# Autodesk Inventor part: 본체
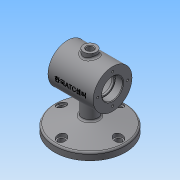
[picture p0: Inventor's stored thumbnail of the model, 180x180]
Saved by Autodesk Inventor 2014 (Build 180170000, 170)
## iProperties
Created: 2018-12
Part Number: 본체
Material: 일반
Document SubType Name: Modeling
Designer: net
Density: 1 g/cm^3
Appearance: 기본값
Mass: 253.122 g
Surface Area: 554.262 cm^2
Volume: 253.122 cm^3
Author: net
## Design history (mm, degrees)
sketch "스케치1"
  geometry: L1 (-35, 0)-(35, 0); L2 (-35, 0)-(-35, 30); L3 (-35, 30)-(35, 30); L4 (35, 30)-(35, 0); L5 (-35, 16)-(-23.3, 16); L6 (-23, 15.7)-(-23, 14); L7 (-23, 14)-(-20, 14); L8 (-20, 14)-(-20, 22); L9 (-17, 25)-(17, 25); L10 (20, 22)-(20, 14); L11 (20, 14)-(23, 14); L12 (23, 14)-(23, 15.7); L13 (23.3, 16)-(35, 16); A1 r 0.3 centre (-23.3, 15.7) between (-23, 15.7) and (-23.3, 16); A2 r 0.3 centre (23.3, 15.7) between (23.3, 16) and (23, 15.7); A3 r 3 centre (17, 22) between (20, 22) and (17, 25); A4 r 3 centre (-17, 22) between (-17, 25) and (-20, 22); 6 further points
  constraints: 26 end point, 10 point on line, 8 point on circle, 8 tangent, 7 parallel, 5 perpendicular, 4 centre point, 2 equal radius, 1 coincident, 1 horizontal, 1 midpoint
  dimensions: "d0" = 70 distance of L1.start L1.end; "d1" = 60 diameter of L3 L1; "d2" = 28 diameter of L7 L1; "d3" = 28 diameter of L11 L1; "d4" = 32 diameter of L5 L1; "d5" = 32 diameter of L13 L1; "d6" = 50 diameter of L9 L1; "d7" = 12 distance of L5.start point (-23, 16); "d8" = 12 distance of point (23, 16) L13.end; "d9" = 40 distance of point (-20, 25) point (20, 25); "d10" = 3 distance of L6.end L7.end; "d11" = 0.3 radius of A1; "d12" = 3 radius of A3
revolve "회전1" sketch "스케치1" stored, may be unused: angle "d13" = 90 deg
sketch "스케치2" dims "d14" = 46
  geometry: C1 r 16 at (0, 0) reference; 2 further points
  constraints: 2 vertical alignment, 1 coincident, 2 other
hole "구멍1" sketch "스케치2" at (0, 23) diameter "d15" = 3.242; stored, may be unused: countersink angle "d19" = 90 deg, drill point angle "d21" = 118 deg; dims "d16" = 8, "d17" = 4, "d18" = 2, "d20" = 10
chamfer "모따기1" distance "d25" = 1; stored, may be unused: second distance "d26" = 2, angle "d27" = 45 deg
node "작업 평면1"
sketch "스케치3"
  geometry: C1 r 55 at (0, 0); 1 further point
  constraints: 1 centre point, 1 coincident
  dimensions: "d29" = 110 diameter of C1
extrude "돌출1" join sketch "스케치3" distance "d30" = 11; taper "d31" = 0 deg
sketch "스케치4"
  geometry: L1 (-75, -55)-(-75, 55) reference; L2 (30, 0)-(-75, 0); L3 (-75, 55)-(-64, 55) reference; L4 (-64, 55)-(-64, -55) reference; L5 (-64, -55)-(-75, -55) reference; L6 (-64, 55)-(-52.478, 12); L7 (-52.478, 12)-(-64, 12); L8 (-64, 55)-(-64, 12); C1 r 25 at (0, 0) reference; 3 further points
  constraints: 8 end point, 2 horizontal alignment, 2 midpoint, 1 collinear, 1 perpendicular, 1 point on line, 1 other
  dimensions: "d39" = 75 deg angle of L6 L3; "d40" = 24 diameter of L6.end L2
revolve "회전2" sketch "스케치4" stored, may be unused: angle "d41" = 90 deg
fillet "모깎기2" dims "d42" = 3
sketch "스케치5"
  geometry: C1 r 12 at (0, 0) reference; C2 r 12 at (0, 0)
  constraints: 1 centre point, 1 coincident, 1 concentric
extrude "돌출2" join sketch "스케치5" stored distance "d43" = 1; taper "d44" = 0 deg
fillet "모깎기3" dims "d45" = 3
node "작업 평면2"
sketch "스케치6"
  geometry: C1 r 10 at (0, 0); 1 further point
  constraints: 1 centre point, 1 coincident
  dimensions: "d47" = 20 diameter of C1
extrude "돌출3" join sketch "스케치6" stored distance "d48" = 1; taper "d49" = 0 deg
sketch "스케치7"
  geometry: C1 r 10 at (0, 0) reference; C2 r 5 at (0, 0)
  constraints: 1 centre point, 1 coincident
  dimensions: "d50" = 10 diameter of C2
extrude "돌출4" cut sketch "스케치7" distance "d51" = 45; taper "d52" = 0 deg
fillet "모깎기4" dims "d53" = 3
sketch "스케치9" dims "d62" = 88
  geometry: C1 r 55 at (0, 0) reference; C2 r 5 at (0, 44); 1 further point
  constraints: 2 vertical alignment, 1 centre point, 1 coincident, 2 other
  dimensions: "d63" = 10 diameter of C2
extrude "돌출5" cut sketch "스케치9" stored distance "d64" = 10; taper "d65" = 0 deg
node "작업 평면3"
sketch "스케치11"
  geometry: C1 r 5 at (0, 44) reference; C2 r 54.703 at (0, 0) reference; C3 r 7 at (0, 44); 1 further point
  constraints: 1 centre point, 1 coincident
  dimensions: "d68" = 14 diameter of C3
extrude "돌출6" cut sketch "스케치11" distance "d69" = 15; taper "d70" = 0 deg
node "작업 평면4"
sketch "스케치12"
  geometry: L1 (35, -30)-(35, 30) reference; L2 (-35, 0)-(35, 0) reference; L3 (46.098, -75)-(-46.098, -75) reference; L4 (-46.098, -75)-(-46.098, -66.302) reference; L5 (46.098, -66.302)-(46.098, -75) reference; 4 further points
  constraints: 2 horizontal alignment, 3 other
  dimensions: "d74" = 35 distance from line of L1 point (0, 0)
feature "엠보싱1" sketch "스케치12" dims "d0" = 70, "d1" = 60, "d2" = 28, "d3" = 28, "d4" = 32, "d5" = 32, "d6" = 50, "d7" = 12, "d8" = 12, "d9" = 40, "d10" = 3, "d11" = 0.3, "d12" = 3, "d75" = 0.5, "d76" = 0
chamfer "모따기2" distance "d77" = 1; stored, may be unused: second distance "d78" = 2, angle "d79" = 45 deg
node "솔리드1"
pattern_circular "원형 패턴1" dims angle "d23" = 360 deg
mirror "대칭1"
pattern_circular "원형 패턴2" dims angle "d72" = 360 deg
node "절단 모서리 투영1"
node "절단 모서리 투영2"
node "절단 모서리 투영3"
other parameters: "d28" = -75, "d46" = 112
